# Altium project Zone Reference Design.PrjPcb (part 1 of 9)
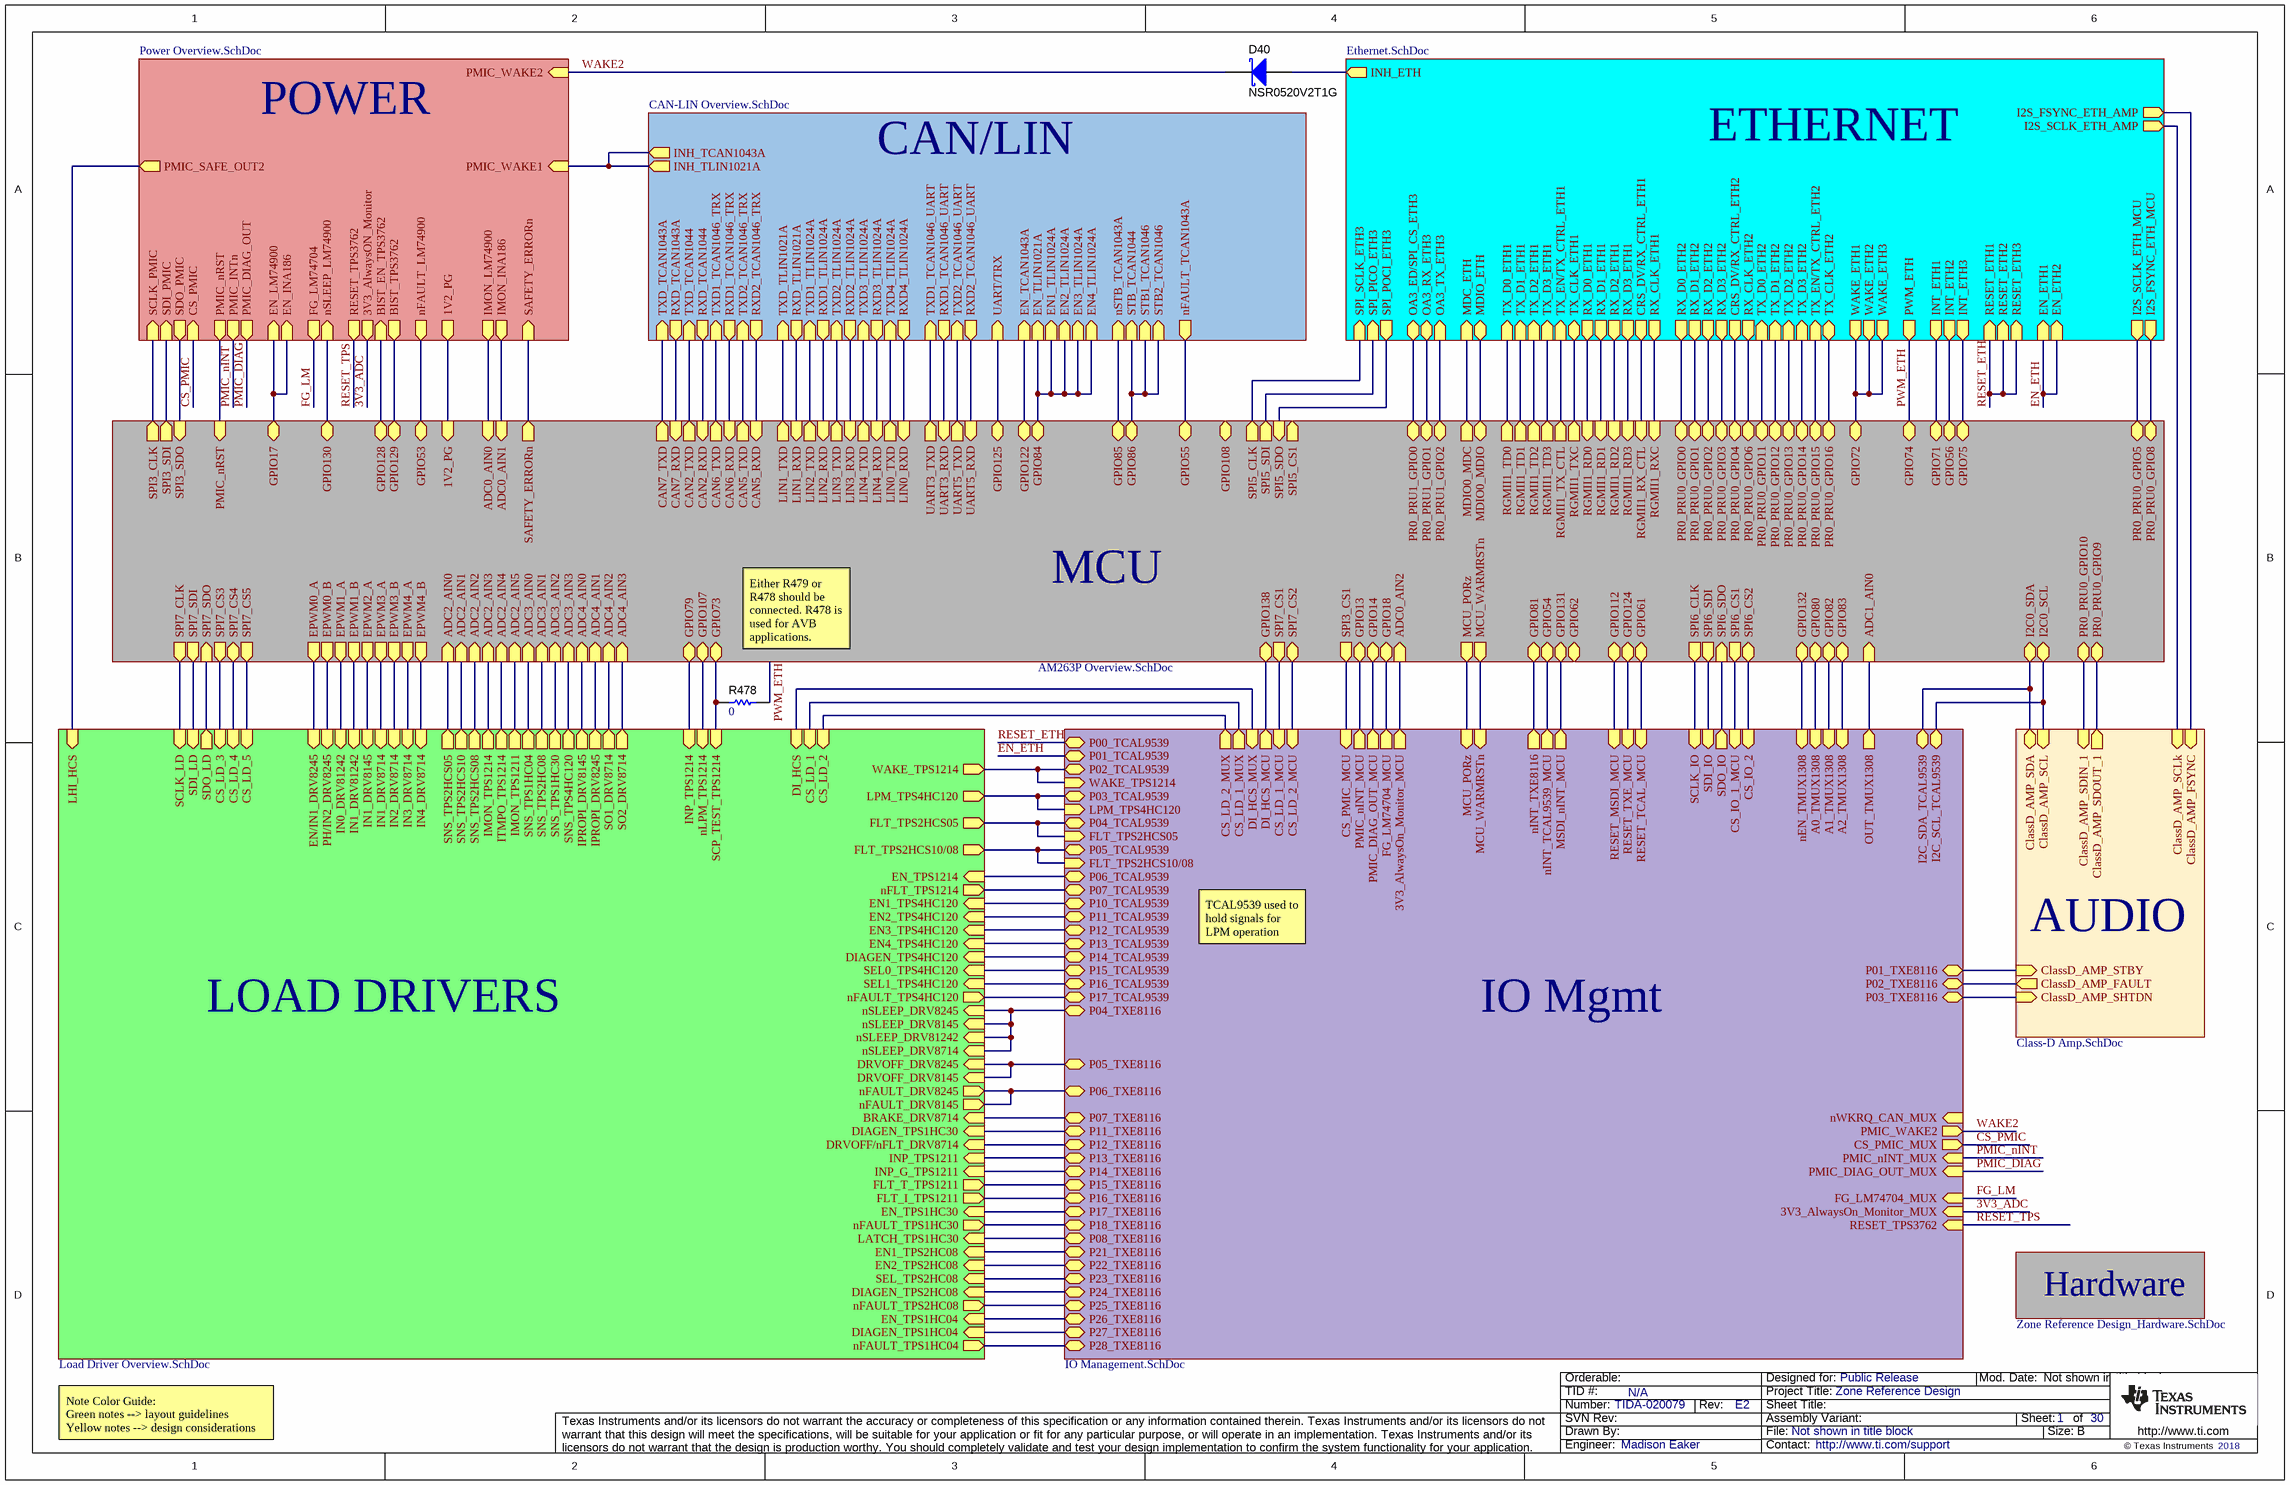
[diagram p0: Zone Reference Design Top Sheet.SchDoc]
CopyrightYear: 2018; PCB_Layout: Krypton Solutions; PCB_Rev: E2; PRJ_Customer: Public Release; PRJ_Engineer: Madison Eaker; PRJ_Number: TIDA-020079; PRJ_Title: Zone Reference Design; SCH_Rev: E2; TechSupport: http://www.ti.com/support; TID: N/A
30 sheets, 1132 parts. Net scope: hierarchical (ports join the sheet entries above them; power ports are global).
Board file: Zone Reference Design.PcbDoc
Sheets:
  Zone Reference Design Top Sheet.SchDoc
    POWER = Power Overview.SchDoc
      Power ORing = Input Supply.SchDoc
      PMIC = PMIC.SchDoc
      Extra Power = BUCKs and LDO.SchDoc
    LOAD DRIVERS = Load Driver Overview.SchDoc
      Standard HSS = High Side Switches.SchDoc
      Half Bridge Gate Driver = DRV8714S-Q1.SchDoc
      H-Bridge, Half Bridge, HS/LS = DRV8x45S-Q1 and DRV81242-Q1.SchDoc
      Standard HSSC = TPS1211-Q1.SchDoc
      Smart Fuse HSS = Smart Fuse HSS.SchDoc
      Smart Fuse HSSC = TPS1214-Q1.SchDoc
    CAN/LIN = CAN-LIN Overview.SchDoc
      TLIN1021A and TLIN1024A = LIN.SchDoc
      TCAN1043A and TCAN1044V = CAN1.SchDoc
      TCAN1046AV = CAN2.SchDoc
    IO Mgmt = IO Management.SchDoc
      MUXes and TPLD = MUXes and TPLD.SchDoc
      MSDI = TIC12400-Q1.SchDoc
      IO Expanders = IO Expanders.SchDoc
    MCU = AM263P Overview.SchDoc
      RESET CIRCUIT = AM263P Reset Circuit.SchDoc
      AM263Px Power Caps = AM263P Power Caps.SchDoc
      Temp Sensor/EEPROM = AM263P Temp and EEPROM.SchDoc
      OSPI Bootmode = AM263P OSPI Bootmode.SchDoc
      ADC = AM263P ADC.SchDoc
      AM263Px IO = AM263P PRU_EPWM.SchDoc
    ETHERNET = Ethernet.SchDoc
    AUDIO = Class-D Amp.SchDoc
    Hardware = Zone Reference Design_Hardware.SchDoc

## Sheet Zone Reference Design Top Sheet.SchDoc
size 431 x 279 mm; Date: Not shown in title block; ApprovedBy: Not shown in title block; CheckedBy: Not shown in title block; Author: Not shown in title block; CompanyName: Not shown in title block; Engineer: Not shown in title block; Organization: Not shown in title block; Address1: Not shown in title block; Address2: Not shown in title block; Address3: Not shown in title block; Address4: Not shown in title block; DocumentNumber: 1; Revision: Use project parameter SCH_Rev; SheetNumber: 1; SheetTotal: 30; PageSetup: Record=PageOptions¦CenterHorizontal=True¦CenterVertical=True¦PrintScale=1.00¦XCorrection=1.00¦YCorrection=1.00¦PrintKind=0¦BorderSize=5000000¦LeftOffset=0¦BottomOffset=0¦Orientation=2¦PaperLength=1000¦PaperWidth=1000¦Scale=100¦PaperSource=15¦PrintQuality=600¦MediaType=1¦DitherType=10¦PaperKind=Letter¦PrintScaleMode=1

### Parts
D40  NSR0520V2T1G  [SOD-523]
R478  ValueDisplayed: 0  [0603]  (hidden comment: RC0603JR-070RL)

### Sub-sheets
AUDIO = Class-D Amp.SchDoc: ClassD_AMP_SHTDN (in), ClassD_AMP_SDA (bidir), ClassD_AMP_SCL (in), ClassD_AMP_STBY (in), ClassD_AMP_FAULT (out), ClassD_AMP_SCLk (in), ClassD_AMP_FSYNC (in), ClassD_AMP_SDIN_1 (in), ClassD_AMP_SDOUT_1 (out)
CAN/LIN = CAN-LIN Overview.SchDoc: TXD_TCAN1043A (in), RXD_TCAN1043A (out), TXD_TCAN1044 (in), RXD_TCAN1044 (out), EN_TCAN1043A (in), nSTB_TCAN1043A (in), STB_TCAN1044 (in), STB1_TCAN1046 (in), STB2_TCAN1046 (in), UART/TRX (in), TXD1_TCAN1046_UART (in), RXD1_TCAN1046_UART (out), TXD1_TCAN1046_TRX (in), RXD1_TCAN1046_TRX (out), TXD2_TCAN1046_UART (in), RXD2_TCAN1046_UART (out), TXD2_TCAN1046_TRX (in), RXD2_TCAN1046_TRX (out), TXD_TLIN1021A (in), RXD_TLIN1021A (out), TXD1_TLIN1024A (in), RXD1_TLIN1024A (out), TXD2_TLIN1024A (in), RXD2_TLIN1024A (out), TXD3_TLIN1024A (in), RXD3_TLIN1024A (out), TXD4_TLIN1024A (in), RXD4_TLIN1024A (out), EN_TLIN1021A (in), EN1_TLIN1024A (in), EN2_TLIN1024A (in), EN3_TLIN1024A (in), EN4_TLIN1024A (in), INH_TCAN1043A (out), nFAULT_TCAN1043A (out), INH_TLIN1021A (out)
ETHERNET = Ethernet.SchDoc: RX_D3_ETH1 (out), RX_D2_ETH1 (out), RX_D1_ETH1 (out), RX_D0_ETH1 (out), RX_CLK_ETH1 (out), CRS_DV/RX_CTRL_ETH1 (out), TX_CLK_ETH1 (bidir), TX_EN/TX_CTRL_ETH1 (in), TX_D3_ETH1 (in), TX_D2_ETH1 (in), TX_D1_ETH1 (in), TX_D0_ETH1 (in), INT_ETH1 (out), WAKE_ETH1 (out), PWM_ETH (out), RESET_ETH1 (in), EN_ETH1 (in), MDIO_ETH (bidir), MDC_ETH (in), INH_ETH (out), RX_D3_ETH2 (out), RX_D2_ETH2 (out), RX_D1_ETH2 (out), RX_D0_ETH2 (out), RX_CLK_ETH2 (out), CRS_DV/RX_CTRL_ETH2 (out), TX_CLK_ETH2 (bidir), TX_EN/TX_CTRL_ETH2 (in), TX_D3_ETH2 (in), TX_D2_ETH2 (in), TX_D1_ETH2 (in), TX_D0_ETH2 (in), SPI_SCLK_ETH3 (in), SPI_PICO_ETH3 (in), SPI_POCI_ETH3 (out), OA3_TX_ETH3 (in), OA3_RX_ETH3 (bidir), INT_ETH3 (out), RESET_ETH3 (in), WAKE_ETH3 (out), INT_ETH2 (out), WAKE_ETH2 (out), RESET_ETH2 (in), EN_ETH2 (in), OA3_ED/SPI_CS_ETH3 (bidir), I2S_FSYNC_ETH_AMP (out), I2S_FSYNC_ETH_MCU (out), I2S_SCLK_ETH_AMP (out), I2S_SCLK_ETH_MCU (out)
Hardware = Zone Reference Design_Hardware.SchDoc: no entries
IO Mgmt = IO Management.SchDoc: SCLK_IO (in), SDI_IO (in), SDO_IO (out), nEN_TMUX1308 (in), A0_TMUX1308 (in), A1_TMUX1308 (in), A2_TMUX1308 (in), OUT_TMUX1308 (out), MSDI_nINT_MCU (out), I2C_SCL_TCAL9539 (bidir), I2C_SDA_TCAL9539 (bidir), PMIC_WAKE2 (out), nINT_TXE8116 (out), CS_IO_2 (in), P01_TXE8116 (bidir), P02_TXE8116 (bidir), P03_TXE8116 (bidir), P04_TXE8116 (bidir), P05_TXE8116 (bidir), P06_TXE8116 (bidir), P07_TXE8116 (bidir), P11_TXE8116 (bidir), P12_TXE8116 (bidir), P13_TXE8116 (bidir), P14_TXE8116 (bidir), P15_TXE8116 (bidir), P16_TXE8116 (bidir), P17_TXE8116 (bidir), P08_TXE8116 (bidir), P18_TXE8116 (bidir), P10_TCAL9539 (bidir), P11_TCAL9539 (bidir), P12_TCAL9539 (bidir), P13_TCAL9539 (bidir), P14_TCAL9539 (bidir), P15_TCAL9539 (bidir), P16_TCAL9539 (bidir), P17_TCAL9539 (bidir), P00_TCAL9539 (bidir), P01_TCAL9539 (bidir), P02_TCAL9539 (bidir), P03_TCAL9539 (bidir), P04_TCAL9539 (bidir), P05_TCAL9539 (bidir), P06_TCAL9539 (bidir), P07_TCAL9539 (bidir), P21_TXE8116 (bidir), P22_TXE8116 (bidir), P23_TXE8116 (bidir), P24_TXE8116 (bidir), P25_TXE8116 (bidir), P26_TXE8116 (bidir), P27_TXE8116 (bidir), P28_TXE8116 (bidir), nINT_TCAL9539_MCU (out), MCU_PORz (in), MCU_WARMRSTn (in), RESET_TCAL_MCU (in), RESET_TXE_MCU (in), DI_HCS_MUX (in), DI_HCS_MCU (out), CS_LD_1_MUX (out), CS_LD_2_MUX (out), CS_PMIC_MUX (out), PMIC_DIAG_OUT_MUX (in), FG_LM74704_MUX (in), 3V3_AlwaysOn_Monitor_MUX (in), LPM_TPS4HC120 (in), WAKE_TPS1214 (in), FLT_TPS2HCS05 (in), RESET_TPS3762 (in), CS_LD_1_MCU (in), CS_LD_2_MCU (in), CS_IO_1_MCU (in), CS_PMIC_MCU (in), PMIC_nINT_MUX (in), PMIC_DIAG_OUT_MCU (out), FG_LM74704_MCU (out), 3V3_AlwaysOn_Monitor_MCU (out), PMIC_nINT_MCU (out), RESET_MSDI_MCU (in), FLT_TPS2HCS10/08  (in), nWKRQ_CAN_MUX (in)
LOAD DRIVERS = Load Driver Overview.SchDoc: SNS_TPS2HCS05 (out), SNS_TPS2HCS10 (out), SNS_TPS2HCS08 (out), IMON_TPS1214 (out), ITMPO_TPS1214 (out), WAKE_TPS1214 (out), FLT_TPS2HCS05 (out), FLT_TPS2HCS10/08 (out), SDO_LD (out), IMON_TPS1211 (out), FLT_T_TPS1211 (out), FLT_I_TPS1211 (out), SNS_TPS4HC120 (out), SNS_TPS1HC30 (out), SNS_TPS2HC08 (out), SNS_TPS1HC04 (out), LPM_TPS4HC120 (out), nFAULT_TPS2HC08 (out), nFAULT_TPS1HC04 (out), SCLK_LD (in), SDI_LD (in), CS_LD_1 (in), CS_LD_2 (in), nLPM_TPS1214 (in), LHI_HCS (in), DI_HCS (in), nFAULT_DRV8245 (out), nFAULT_DRV8145 (out), IPROPI_DRV8145 (out), IPROPI_DRV8245 (out), CS_LD_3 (in), CS_LD_4 (in), EN/IN1_DRV8245 (in), PH/IN2_DRV8245 (in), IN1_DRV8145 (in), IN0_DRV81242 (in), IN1_DRV81242 (in), CS_LD_5 (in), IN1_DRV8714 (in), IN2_DRV8714 (in), IN3_DRV8714 (in), IN4_DRV8714 (in), DRVOFF/nFLT_DRV8714 (in), EN1_TPS4HC120 (in), EN2_TPS4HC120 (in), EN3_TPS4HC120 (in), EN4_TPS4HC120 (in), SEL1_TPS4HC120 (in), SEL0_TPS4HC120 (in), SO1_DRV8714 (out), SO2_DRV8714 (out), nFLT_TPS1214 (out), EN_TPS1HC30 (in), LATCH_TPS1HC30 (in), EN1_TPS2HC08 (in), EN2_TPS2HC08 (in), SEL_TPS2HC08 (in), DIAGEN_TPS2HC08 (in), EN_TPS1HC04 (in), DIAGEN_TPS1HC04 (in), DIAGEN_TPS4HC120 (in), DIAGEN_TPS1HC30 (in), BRAKE_DRV8714 (in), nFAULT_TPS1HC30 (out), nFAULT_TPS4HC120 (out), EN_TPS1214 (in), INP_TPS1214 (in), SCP_TEST_TPS1214 (in), INP_TPS1211 (in), INP_G_TPS1211 (in), nSLEEP_DRV8245 (in), nSLEEP_DRV8145 (in), nSLEEP_DRV81242 (in), DRVOFF_DRV8245 (in), DRVOFF_DRV8145 (in), nSLEEP_DRV8714 (in)
MCU = AM263P Overview.SchDoc: LIN1_RXD (in), LIN1_TXD (out), LIN2_RXD (in), LIN2_TXD (out), LIN3_RXD (in), LIN3_TXD (out), LIN4_RXD (in), LIN4_TXD (out), LIN0_RXD (in), LIN0_TXD (out), CAN7_RXD (in), CAN7_TXD (out), CAN2_RXD (in), CAN2_TXD (out), CAN6_RXD (in), CAN6_TXD (out), CAN5_RXD (in), CAN5_TXD (out), UART3_RXD (in), UART3_TXD (out), UART5_RXD (in), UART5_TXD (out), I2C0_SCL (bidir), I2C0_SDA (bidir), SPI5_CLK (out), SPI5_CS1 (out), SPI5_SDI (out), SPI5_SDO (in), SPI7_CLK (out), SPI7_CS1 (out), SPI7_SDI (out), SPI7_SDO (in), SPI3_CLK (out), SPI3_CS1 (out), SPI3_SDI (out), SPI3_SDO (in), SPI6_CLK (out), SPI6_CS1 (out), SPI6_SDI (out), SPI6_SDO (in), EPWM0_A (out), EPWM0_B (out), EPWM1_A (out), EPWM1_B (out), EPWM2_A (out), EPWM3_A (out), EPWM3_B (out), EPWM4_A (out), EPWM4_B (out), GPIO53 (bidir), GPIO54 (bidir), GPIO55 (bidir), GPIO56 (bidir), ADC0_AIN0 (in), ADC0_AIN1 (in), ADC1_AIN0 (in), ADC2_AIN0 (in), ADC2_AIN1 (in), ADC2_AIN2 (in), ADC2_AIN3 (in), ADC2_AIN4 (in), ADC2_AIN5 (in), ADC4_AIN0 (in), ADC4_AIN1 (in), ADC4_AIN2 (in), ADC4_AIN3 (in), ADC3_AIN0 (in), ADC3_AIN1 (in), ADC3_AIN2 (in), ADC3_AIN3 (in), SPI7_CS2 (bidir), GPIO17 (bidir), GPIO18 (bidir), GPIO79 (bidir), SPI6_CS2 (bidir), GPIO61 (bidir), GPIO62 (bidir), SPI7_CS3 (out), SPI7_CS4 (bidir), GPIO71 (bidir), GPIO72 (bidir), GPIO73 (bidir), GPIO74 (bidir), GPIO80 (bidir), GPIO82 (bidir), GPIO83 (bidir), GPIO84 (bidir), GPIO107 (bidir), GPIO108 (bidir), GPIO112 (bidir), GPIO122 (bidir), GPIO124 (bidir), GPIO125 (bidir), GPIO129 (bidir), GPIO130 (bidir), GPIO131 (bidir), GPIO132 (bidir), GPIO138 (bidir), GPIO81 (bidir), SAFETY_ERRORn (out), MDIO0_MDC (out), MDIO0_MDIO (bidir), RGMII1_RD0 (in), RGMII1_RD2 (in), RGMII1_RD1 (in), RGMII1_RD3 (in), RGMII1_RX_CTL (in), RGMII1_RXC (in), RGMII1_TD0 (out), RGMII1_TD1 (out), RGMII1_TD2 (out), RGMII1_TD3 (out), RGMII1_TX_CTL (out), RGMII1_TXC (out), GPIO86 (bidir), GPIO85 (bidir), PR0_PRU0_GPIO0 (bidir), PR0_PRU0_GPIO1 (bidir), PR0_PRU0_GPIO2 (bidir), PR0_PRU0_GPIO3 (bidir), PR0_PRU0_GPIO4 (bidir), PR0_PRU0_GPIO5 (bidir), PR0_PRU0_GPIO6 (bidir), PR0_PRU0_GPIO8 (bidir), PR0_PRU0_GPIO9 (bidir), PR0_PRU0_GPIO10 (bidir), PR0_PRU0_GPIO11 (bidir), PR0_PRU0_GPIO12 (bidir), PR0_PRU0_GPIO13 (bidir), PR0_PRU0_GPIO14 (bidir), PR0_PRU0_GPIO15 (bidir), PR0_PRU0_GPIO16 (bidir), PR0_PRU1_GPIO0 (bidir), PR0_PRU1_GPIO1 (bidir), PR0_PRU1_GPIO2 (bidir), PMIC_nRST (in), 1V2_PG (in), GPIO13 (bidir), GPIO14 (bidir), SPI7_CS5 (out), GPIO128 (bidir), GPIO75 (bidir), MCU_PORz (out), MCU_WARMRSTn (out), ADC0_AIN2 (in)
POWER = Power Overview.SchDoc: EN_LM74900 (in), EN_INA186 (in), nSLEEP_LM74900 (in), IMON_INA186 (out), IMON_LM74900 (out), FG_LM74704 (out), nFAULT_LM74900 (out), SCLK_PMIC (in), SDI_PMIC (in), CS_PMIC (in), PMIC_WAKE2 (in), PMIC_WAKE1 (in), SAFETY_ERRORn (in), BIST_EN_TPS3762 (in), RESET_TPS3762 (out), BIST_TPS3762 (out), 1V2_PG (out), PMIC_SAFE_OUT2 (out), PMIC_nRST (out), PMIC_INTn (out), PMIC_DIAG_OUT (out), SDO_PMIC (out), 3V3_AlwaysON_Monitor (out)

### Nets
1V2_PG: sheet POWER/1V2_PG, sheet MCU/1V2_PG
3V3_ADC: sheet POWER/3V3_AlwaysON_Monitor, sheet IO Mgmt/3V3_AlwaysOn_Monitor_MUX
3V3_AlwaysOn_Monitor_MCU: sheet IO Mgmt/3V3_AlwaysOn_Monitor_MCU, sheet MCU/ADC0_AIN2
A0_TMUX1308: sheet IO Mgmt/A0_TMUX1308, sheet MCU/GPIO80
A1_TMUX1308: sheet IO Mgmt/A1_TMUX1308, sheet MCU/GPIO82
A2_TMUX1308: sheet IO Mgmt/A2_TMUX1308, sheet MCU/GPIO83
ADC0_AIN0: sheet POWER/IMON_LM74900, sheet MCU/ADC0_AIN0
ADC0_AIN1: sheet POWER/IMON_INA186, sheet MCU/ADC0_AIN1
ADC1_AIN0: sheet IO Mgmt/OUT_TMUX1308, sheet MCU/ADC1_AIN0
ADC2_AIN0: sheet LOAD DRIVERS/SNS_TPS2HCS05, sheet MCU/ADC2_AIN0
ADC2_AIN1: sheet LOAD DRIVERS/SNS_TPS2HCS10, sheet MCU/ADC2_AIN1
ADC2_AIN2: sheet LOAD DRIVERS/SNS_TPS2HCS08, sheet MCU/ADC2_AIN2
ADC2_AIN5: sheet LOAD DRIVERS/IMON_TPS1211, sheet MCU/ADC2_AIN5
ADC3_AIN0: sheet LOAD DRIVERS/SNS_TPS1HC04, sheet MCU/ADC3_AIN0
ADC3_AIN1: sheet LOAD DRIVERS/SNS_TPS2HC08, sheet MCU/ADC3_AIN1
ADC3_AIN2: sheet LOAD DRIVERS/SNS_TPS1HC30, sheet MCU/ADC3_AIN2
ADC3_AIN3: sheet LOAD DRIVERS/SNS_TPS4HC120, sheet MCU/ADC3_AIN3
ADC4_AIN0: sheet LOAD DRIVERS/IPROPI_DRV8145, sheet MCU/ADC4_AIN0
ADC4_AIN1: sheet LOAD DRIVERS/IPROPI_DRV8245, sheet MCU/ADC4_AIN1
ADC4_AIN2: sheet LOAD DRIVERS/SO1_DRV8714, sheet MCU/ADC4_AIN2
ADC4_AIN3: sheet LOAD DRIVERS/SO2_DRV8714, sheet MCU/ADC4_AIN3
BIST_EN_TPS3762: sheet POWER/BIST_EN_TPS3762, sheet MCU/GPIO128
BIST_TPS3762: sheet POWER/BIST_TPS3762, sheet MCU/GPIO129
BRAKE_DRV8714: sheet LOAD DRIVERS/BRAKE_DRV8714, sheet IO Mgmt/P07_TXE8116
CAN2_RXD: sheet CAN/LIN/RXD_TCAN1044, sheet MCU/CAN2_RXD
CAN2_TXD: sheet CAN/LIN/TXD_TCAN1044, sheet MCU/CAN2_TXD
CAN5_RXD: sheet CAN/LIN/RXD2_TCAN1046_TRX, sheet MCU/CAN5_RXD
CAN5_TXD: sheet CAN/LIN/TXD2_TCAN1046_TRX, sheet MCU/CAN5_TXD
CAN6_RXD: sheet CAN/LIN/RXD1_TCAN1046_TRX, sheet MCU/CAN6_RXD
CAN6_TXD: sheet CAN/LIN/TXD1_TCAN1046_TRX, sheet MCU/CAN6_TXD
CAN7_RXD: sheet CAN/LIN/RXD_TCAN1043A, sheet MCU/CAN7_RXD
CAN7_TXD: sheet CAN/LIN/TXD_TCAN1043A, sheet MCU/CAN7_TXD
ClassD_AMP_FAULT: sheet IO Mgmt/P02_TXE8116, sheet AUDIO/ClassD_AMP_FAULT
ClassD_AMP_FSYNC: sheet ETHERNET/I2S_FSYNC_ETH_AMP, sheet AUDIO/ClassD_AMP_FSYNC
ClassD_AMP_SCLk: sheet ETHERNET/I2S_SCLK_ETH_AMP, sheet AUDIO/ClassD_AMP_SCLk
ClassD_AMP_SDIN_1: sheet MCU/PR0_PRU0_GPIO10, sheet AUDIO/ClassD_AMP_SDIN_1
ClassD_AMP_SDOUT_1: sheet MCU/PR0_PRU0_GPIO9, sheet AUDIO/ClassD_AMP_SDOUT_1
ClassD_AMP_SHTDN: sheet IO Mgmt/P03_TXE8116, sheet AUDIO/ClassD_AMP_SHTDN
ClassD_AMP_STBY: sheet IO Mgmt/P01_TXE8116, sheet AUDIO/ClassD_AMP_STBY
CRS_DV/RX_CTRL_ETH1: sheet MCU/RGMII1_RX_CTL, sheet ETHERNET/CRS_DV/RX_CTRL_ETH1
CRS_DV/RX_CTRL_ETH2: sheet MCU/PR0_PRU0_GPIO4, sheet ETHERNET/CRS_DV/RX_CTRL_ETH2
CS_IO: sheet IO Mgmt/CS_IO_2, sheet MCU/SPI6_CS2
CS_IO_1_MCU: sheet IO Mgmt/CS_IO_1_MCU, sheet MCU/SPI6_CS1
CS_LD_1: sheet LOAD DRIVERS/CS_LD_1, sheet IO Mgmt/CS_LD_1_MUX
CS_LD_1_MCU: sheet IO Mgmt/CS_LD_1_MCU, sheet MCU/SPI7_CS1
CS_LD_2: sheet LOAD DRIVERS/CS_LD_2, sheet IO Mgmt/CS_LD_2_MUX
CS_LD_4: sheet LOAD DRIVERS/CS_LD_4, sheet MCU/SPI7_CS4
CS_PMIC: sheet POWER/CS_PMIC, sheet IO Mgmt/CS_PMIC_MUX
CS_PMIC_MCU: sheet IO Mgmt/CS_PMIC_MCU, sheet MCU/SPI3_CS1
DI_HCS: sheet LOAD DRIVERS/DI_HCS, sheet IO Mgmt/DI_HCS_MUX
DI_HCS_MCU: sheet IO Mgmt/DI_HCS_MCU, sheet MCU/GPIO138
DIAGEN_TPS1HC04: sheet LOAD DRIVERS/DIAGEN_TPS1HC04, sheet IO Mgmt/P27_TXE8116
DIAGEN_TPS1HC30: sheet LOAD DRIVERS/DIAGEN_TPS1HC30, sheet IO Mgmt/P11_TXE8116
DIAGEN_TPS2HC08: sheet LOAD DRIVERS/DIAGEN_TPS2HC08, sheet IO Mgmt/P24_TXE8116
DIAGEN_TPS4HC120: sheet LOAD DRIVERS/DIAGEN_TPS4HC120, sheet IO Mgmt/P14_TCAL9539
DRVOFF_DRV8145: sheet LOAD DRIVERS/DRVOFF_DRV8245, sheet LOAD DRIVERS/DRVOFF_DRV8145, sheet IO Mgmt/P05_TXE8116
EN1_TLIN1024A: sheet CAN/LIN/EN_TLIN1021A, sheet CAN/LIN/EN1_TLIN1024A, sheet CAN/LIN/EN2_TLIN1024A, sheet CAN/LIN/EN3_TLIN1024A, sheet CAN/LIN/EN4_TLIN1024A, sheet MCU/GPIO84
EN1_TPS2HC08: sheet LOAD DRIVERS/EN1_TPS2HC08, sheet IO Mgmt/P21_TXE8116
EN1_TPS4HC120: sheet LOAD DRIVERS/EN1_TPS4HC120, sheet IO Mgmt/P10_TCAL9539
EN2_TPS2HC08: sheet LOAD DRIVERS/EN2_TPS2HC08, sheet IO Mgmt/P22_TXE8116
EN2_TPS4HC120: sheet LOAD DRIVERS/EN2_TPS4HC120, sheet IO Mgmt/P11_TCAL9539
EN3_TPS4HC120: sheet LOAD DRIVERS/EN3_TPS4HC120, sheet IO Mgmt/P12_TCAL9539
EN4_TPS4HC120: sheet LOAD DRIVERS/EN4_TPS4HC120, sheet IO Mgmt/P13_TCAL9539
EN/IN1_DRV8245: sheet LOAD DRIVERS/EN/IN1_DRV8245, sheet MCU/EPWM0_A
EN_ETH: sheet IO Mgmt/P01_TCAL9539, sheet ETHERNET/EN_ETH1, sheet ETHERNET/EN_ETH2
EN_INA186: sheet POWER/EN_LM74900, sheet POWER/EN_INA186, sheet MCU/GPIO17
EN_TCAN1043A: sheet CAN/LIN/EN_TCAN1043A, sheet MCU/GPIO122
EN_TPS1HC04: sheet LOAD DRIVERS/EN_TPS1HC04, sheet IO Mgmt/P26_TXE8116
EN_TPS1HC30: sheet LOAD DRIVERS/EN_TPS1HC30, sheet IO Mgmt/P17_TXE8116
EN_TPS1214: sheet LOAD DRIVERS/EN_TPS1214, sheet IO Mgmt/P06_TCAL9539
EPWM0_B: sheet LOAD DRIVERS/PH/IN2_DRV8245, sheet MCU/EPWM0_B
EPWM1_A: sheet LOAD DRIVERS/IN0_DRV81242, sheet MCU/EPWM1_A
EPWM1_B: sheet LOAD DRIVERS/IN1_DRV81242, sheet MCU/EPWM1_B
EPWM2_A: sheet LOAD DRIVERS/IN1_DRV8145, sheet MCU/EPWM2_A
EPWM3_A: sheet LOAD DRIVERS/IN1_DRV8714, sheet MCU/EPWM3_A
EPWM3_B: sheet LOAD DRIVERS/IN2_DRV8714, sheet MCU/EPWM3_B
EPWM4_A: sheet LOAD DRIVERS/IN3_DRV8714, sheet MCU/EPWM4_A
EPWM4_B: sheet LOAD DRIVERS/IN4_DRV8714, sheet MCU/EPWM4_B
EPWM5_A: sheet POWER/nFAULT_LM74900, sheet MCU/GPIO53
EPWM5_B: sheet IO Mgmt/nINT_TCAL9539_MCU, sheet MCU/GPIO54
EPWM6_A: sheet CAN/LIN/nFAULT_TCAN1043A, sheet MCU/GPIO55
EPWM6_B: sheet MCU/GPIO56, sheet ETHERNET/INT_ETH2
EPWM9_A: sheet IO Mgmt/RESET_TCAL_MCU, sheet MCU/GPIO61
EPWM_14A: sheet MCU/GPIO71, sheet ETHERNET/INT_ETH1
EPWM_14B: sheet MCU/GPIO72, sheet ETHERNET/WAKE_ETH1, sheet ETHERNET/WAKE_ETH3, sheet ETHERNET/WAKE_ETH2
EPWM_15A: R478.1 ; sheet LOAD DRIVERS/SCP_TEST_TPS1214, sheet MCU/GPIO73
EQEP0_A: sheet POWER/nSLEEP_LM74900, sheet MCU/GPIO130
EQEP0_B: sheet IO Mgmt/MSDI_nINT_MCU, sheet MCU/GPIO131
EQEP0_STROBE: sheet IO Mgmt/nEN_TMUX1308, sheet MCU/GPIO132
FG_LM: sheet POWER/FG_LM74704, sheet IO Mgmt/FG_LM74704_MUX  [project net FETGOOD]
FG_LM74704_MCU: sheet IO Mgmt/FG_LM74704_MCU, sheet MCU/GPIO18
FLT/: sheet LOAD DRIVERS/nFLT_TPS1214, sheet IO Mgmt/P07_TCAL9539
FLT_I_TPS1211: sheet LOAD DRIVERS/FLT_I_TPS1211, sheet IO Mgmt/P16_TXE8116
FLT_T_TPS1211: sheet LOAD DRIVERS/FLT_T_TPS1211, sheet IO Mgmt/P15_TXE8116
FLT_TPS2HCS05: sheet LOAD DRIVERS/FLT_TPS2HCS05, sheet IO Mgmt/P04_TCAL9539, sheet IO Mgmt/FLT_TPS2HCS05
FLT_TPS2HCS10/08: sheet LOAD DRIVERS/FLT_TPS2HCS10/08, sheet IO Mgmt/P05_TCAL9539, sheet IO Mgmt/FLT_TPS2HCS10/08 
GPIO14: sheet IO Mgmt/PMIC_DIAG_OUT_MCU, sheet MCU/GPIO14
GPIO75: sheet MCU/GPIO75, sheet ETHERNET/INT_ETH3
GPIO79: sheet LOAD DRIVERS/INP_TPS1214, sheet MCU/GPIO79
GPIO81: sheet IO Mgmt/nINT_TXE8116, sheet MCU/GPIO81
GPIO85: sheet CAN/LIN/nSTB_TCAN1043A, sheet MCU/GPIO85
GPIO86: sheet CAN/LIN/STB_TCAN1044, sheet CAN/LIN/STB1_TCAN1046, sheet CAN/LIN/STB2_TCAN1046, sheet MCU/GPIO86
GPIO107: sheet LOAD DRIVERS/nLPM_TPS1214, sheet MCU/GPIO107
GPIO112: sheet IO Mgmt/RESET_MSDI_MCU, sheet MCU/GPIO112
GPIO124: sheet IO Mgmt/RESET_TXE_MCU, sheet MCU/GPIO124
GPIO125: sheet CAN/LIN/UART/TRX, sheet MCU/GPIO125
I2C0_SCL: sheet IO Mgmt/I2C_SCL_TCAL9539, sheet MCU/I2C0_SCL, sheet AUDIO/ClassD_AMP_SCL
I2C0_SDA: sheet IO Mgmt/I2C_SDA_TCAL9539, sheet MCU/I2C0_SDA, sheet AUDIO/ClassD_AMP_SDA
I2S_FSYNC_ETH_MCU: sheet MCU/PR0_PRU0_GPIO8, sheet ETHERNET/I2S_FSYNC_ETH_MCU
I2S_SCLK_ETH_MCU: sheet MCU/PR0_PRU0_GPIO5, sheet ETHERNET/I2S_SCLK_ETH_MCU
IMON: sheet LOAD DRIVERS/IMON_TPS1214, sheet MCU/ADC2_AIN3
INH_ETH: D40.2(A) ; sheet ETHERNET/INH_ETH
INH_TCAN1043A: sheet POWER/PMIC_WAKE1, sheet CAN/LIN/INH_TCAN1043A, sheet CAN/LIN/INH_TLIN1021A
INP_G_TPS1211: sheet LOAD DRIVERS/INP_G_TPS1211, sheet IO Mgmt/P14_TXE8116
INP_TPS1211: sheet LOAD DRIVERS/INP_TPS1211, sheet IO Mgmt/P13_TXE8116
ITMPO: sheet LOAD DRIVERS/ITMPO_TPS1214, sheet MCU/ADC2_AIN4
LATCH_TPS1HC30: sheet LOAD DRIVERS/LATCH_TPS1HC30, sheet IO Mgmt/P08_TXE8116
LHI_HCS: sheet POWER/PMIC_SAFE_OUT2, sheet LOAD DRIVERS/LHI_HCS
LIN0_RXD: sheet CAN/LIN/RXD4_TLIN1024A, sheet MCU/LIN0_RXD
LIN0_TXD: sheet CAN/LIN/TXD4_TLIN1024A, sheet MCU/LIN0_TXD
LIN1_RXD: sheet CAN/LIN/RXD_TLIN1021A, sheet MCU/LIN1_RXD
LIN1_TXD: sheet CAN/LIN/TXD_TLIN1021A, sheet MCU/LIN1_TXD
LIN2_RXD: sheet CAN/LIN/RXD1_TLIN1024A, sheet MCU/LIN2_RXD
LIN2_TXD: sheet CAN/LIN/TXD1_TLIN1024A, sheet MCU/LIN2_TXD
LIN3_RXD: sheet CAN/LIN/RXD2_TLIN1024A, sheet MCU/LIN3_RXD
LIN4_RXD: sheet CAN/LIN/RXD3_TLIN1024A, sheet MCU/LIN4_RXD
LIN4_TXD: sheet CAN/LIN/TXD3_TLIN1024A, sheet MCU/LIN4_TXD
LPM_TPS4HC120: sheet LOAD DRIVERS/LPM_TPS4HC120, sheet IO Mgmt/P03_TCAL9539, sheet IO Mgmt/LPM_TPS4HC120
MCU_PORz: sheet IO Mgmt/MCU_PORz, sheet MCU/MCU_PORz
MCU_WARMRSTn: sheet IO Mgmt/MCU_WARMRSTn, sheet MCU/MCU_WARMRSTn
MDC_ETH: sheet MCU/MDIO0_MDC, sheet ETHERNET/MDC_ETH
MDIO_ETH: sheet MCU/MDIO0_MDIO, sheet ETHERNET/MDIO_ETH
nCS: sheet LOAD DRIVERS/CS_LD_3, sheet MCU/SPI7_CS3
nFAULT_DRV8145: sheet LOAD DRIVERS/nFAULT_DRV8245, sheet LOAD DRIVERS/nFAULT_DRV8145, sheet IO Mgmt/P06_TXE8116
nFAULT_TPS1HC04: sheet LOAD DRIVERS/nFAULT_TPS1HC04, sheet IO Mgmt/P28_TXE8116
nFAULT_TPS1HC30: sheet LOAD DRIVERS/nFAULT_TPS1HC30, sheet IO Mgmt/P18_TXE8116
nFAULT_TPS2HC08: sheet LOAD DRIVERS/nFAULT_TPS2HC08, sheet IO Mgmt/P25_TXE8116
nFAULT_TPS4HC120: sheet LOAD DRIVERS/nFAULT_TPS4HC120, sheet IO Mgmt/P17_TCAL9539
nFLT_DRV8714: sheet LOAD DRIVERS/DRVOFF/nFLT_DRV8714, sheet IO Mgmt/P12_TXE8116
nSLEEP_DRV81242: sheet LOAD DRIVERS/nSLEEP_DRV8245, sheet LOAD DRIVERS/nSLEEP_DRV8145, sheet LOAD DRIVERS/nSLEEP_DRV81242, sheet LOAD DRIVERS/nSLEEP_DRV8714, sheet IO Mgmt/P04_TXE8116
OA3_ED/SPI_CS_ETH3: sheet MCU/PR0_PRU1_GPIO0, sheet ETHERNET/OA3_ED/SPI_CS_ETH3
OA3_RX_ETH3: sheet MCU/PR0_PRU1_GPIO1, sheet ETHERNET/OA3_RX_ETH3
OA3_TX_ETH3: sheet MCU/PR0_PRU1_GPIO2, sheet ETHERNET/OA3_TX_ETH3
P15_TCAL9539: sheet LOAD DRIVERS/SEL0_TPS4HC120, sheet IO Mgmt/P15_TCAL9539
P16_TCAL9539: sheet LOAD DRIVERS/SEL1_TPS4HC120, sheet IO Mgmt/P16_TCAL9539
P23_TXE8116: sheet LOAD DRIVERS/SEL_TPS2HC08, sheet IO Mgmt/P23_TXE8116
PMIC_DIAG: sheet POWER/PMIC_DIAG_OUT, sheet IO Mgmt/PMIC_DIAG_OUT_MUX
PMIC_nINT: sheet POWER/PMIC_INTn, sheet IO Mgmt/PMIC_nINT_MUX
PMIC_nRST: sheet POWER/PMIC_nRST, sheet MCU/PMIC_nRST
PR0_PRU0_GPIO0: sheet MCU/PR0_PRU0_GPIO0, sheet ETHERNET/RX_D0_ETH2
PR0_PRU0_GPIO1: sheet MCU/PR0_PRU0_GPIO1, sheet ETHERNET/RX_D1_ETH2
PR0_PRU0_GPIO2: sheet MCU/PR0_PRU0_GPIO2, sheet ETHERNET/RX_D2_ETH2
PR0_PRU0_GPIO3: sheet MCU/PR0_PRU0_GPIO3, sheet ETHERNET/RX_D3_ETH2
PR0_PRU0_GPIO6: sheet MCU/PR0_PRU0_GPIO6, sheet ETHERNET/RX_CLK_ETH2
PR0_PRU0_GPIO11: sheet MCU/PR0_PRU0_GPIO11, sheet ETHERNET/TX_D0_ETH2
PR0_PRU0_GPIO12: sheet MCU/PR0_PRU0_GPIO12, sheet ETHERNET/TX_D1_ETH2
PR0_PRU0_GPIO13: sheet MCU/PR0_PRU0_GPIO13, sheet ETHERNET/TX_D2_ETH2
PR0_PRU0_GPIO14: sheet MCU/PR0_PRU0_GPIO14, sheet ETHERNET/TX_D3_ETH2
PR0_PRU0_GPIO15: sheet MCU/PR0_PRU0_GPIO15, sheet ETHERNET/TX_EN/TX_CTRL_ETH2
PR0_PRU0_GPIO16: sheet MCU/PR0_PRU0_GPIO16, sheet ETHERNET/TX_CLK_ETH2
PR0_PRU1_GPIO8: sheet MCU/SPI5_SDO, sheet ETHERNET/SPI_POCI_ETH3
PR0_PRU1_GPIO18: sheet CAN/LIN/TXD1_TCAN1046_UART, sheet MCU/UART3_TXD
PR0_PRU1_GPIO19: sheet CAN/LIN/RXD1_TCAN1046_UART, sheet MCU/UART3_RXD
PWM_ETH: R478.2 ; sheet MCU/GPIO74, sheet ETHERNET/PWM_ETH
RESET_ETH: sheet IO Mgmt/P00_TCAL9539, sheet ETHERNET/RESET_ETH1, sheet ETHERNET/RESET_ETH3, sheet ETHERNET/RESET_ETH2
RESET_TPS: sheet POWER/RESET_TPS3762, sheet IO Mgmt/RESET_TPS3762
RGMII1_RD0: sheet MCU/RGMII1_RD0, sheet ETHERNET/RX_D0_ETH1
RGMII1_RD1: sheet MCU/RGMII1_RD1, sheet ETHERNET/RX_D1_ETH1
RGMII1_RD2: sheet MCU/RGMII1_RD2, sheet ETHERNET/RX_D2_ETH1
RGMII1_RD3: sheet MCU/RGMII1_RD3, sheet ETHERNET/RX_D3_ETH1
RGMII1_RXC: sheet MCU/RGMII1_RXC, sheet ETHERNET/RX_CLK_ETH1
RGMII1_TD0: sheet MCU/RGMII1_TD0, sheet ETHERNET/TX_D0_ETH1
RGMII1_TD1: sheet MCU/RGMII1_TD1, sheet ETHERNET/TX_D1_ETH1
RGMII1_TD2: sheet MCU/RGMII1_TD2, sheet ETHERNET/TX_D2_ETH1
RGMII1_TD3: sheet MCU/RGMII1_TD3, sheet ETHERNET/TX_D3_ETH1
RGMII1_TX_CTL: sheet MCU/RGMII1_TX_CTL, sheet ETHERNET/TX_EN/TX_CTRL_ETH1
RGMII1_TXC: sheet MCU/RGMII1_TXC, sheet ETHERNET/TX_CLK_ETH1
RXD2_TCAN1046_UART: sheet CAN/LIN/RXD2_TCAN1046_UART, sheet MCU/UART5_RXD
SAFETY_ERRORn: sheet POWER/SAFETY_ERRORn, sheet MCU/SAFETY_ERRORn
SCLK: sheet LOAD DRIVERS/SCLK_LD, sheet MCU/SPI7_CLK
SCLK_IO: sheet IO Mgmt/SCLK_IO, sheet MCU/SPI6_CLK
SCLK_PMIC: sheet POWER/SCLK_PMIC, sheet MCU/SPI3_CLK
SDFM_CLK2: sheet CAN/LIN/TXD2_TCAN1046_UART, sheet MCU/UART5_TXD
SDI: sheet LOAD DRIVERS/SDI_LD, sheet MCU/SPI7_SDI
SDI_IO: sheet IO Mgmt/SDI_IO, sheet MCU/SPI6_SDI
SDI_PMIC: sheet POWER/SDI_PMIC, sheet MCU/SPI3_SDI
SDO_IO: sheet IO Mgmt/SDO_IO, sheet MCU/SPI6_SDO
SDO_LD: sheet LOAD DRIVERS/SDO_LD, sheet MCU/SPI7_SDO
SDO_PMIC: sheet POWER/SDO_PMIC, sheet MCU/SPI3_SDO
SPI0_CLK: sheet CAN/LIN/TXD2_TLIN1024A, sheet MCU/LIN3_TXD
SPI0_D0: sheet IO Mgmt/PMIC_nINT_MCU, sheet MCU/GPIO13
SPI5_CLK: sheet MCU/SPI5_CLK, sheet ETHERNET/SPI_SCLK_ETH3
SPI5_SDI: sheet MCU/SPI5_SDI, sheet ETHERNET/SPI_PICO_ETH3
SPI7_CS2: sheet IO Mgmt/CS_LD_2_MCU, sheet MCU/SPI7_CS2
SPI7_CS5: sheet LOAD DRIVERS/CS_LD_5, sheet MCU/SPI7_CS5
WAKE: sheet LOAD DRIVERS/WAKE_TPS1214, sheet IO Mgmt/P02_TCAL9539, sheet IO Mgmt/WAKE_TPS1214
WAKE2: D40.1(K) ; sheet POWER/PMIC_WAKE2, sheet IO Mgmt/PMIC_WAKE2

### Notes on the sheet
- Either R479 or R478 should be connected. R478 is used for AVB applications.
- TCAL9539 used to hold signals for LPM operation
- Note Color Guide:
  Green notes --> layout guidelines
  Yellow notes --> design considerations

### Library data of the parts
D40 = CMP-0028880-3: Diode, Schottky, 20 V, 0.5 A, AEC-Q101, SOD-523; Manufacturer: ON Semiconductor; Green_Lifecycle: Not Set; Vr_V: 20V; TJmax_C: 125°C; SizeArea_mm2: 1.53; SizeZ_mm: 0.65; Green_REACh: Incomplete; AEC Qualified: Y; AEC Category: Q101; Io_A: 500mA; Value: 20V; Vf_V: 480mV; Value1: 0.5A; SizeY_mm: 0.9; SizeX_mm: 1.7; Value2: 0.48V; SizeAreaWB_mm2: 5.13
R478 = CMP-0025885-5: RES, 0, 5%, 0.1 W, 0603; Manufacturer: Yageo; Power_W: 100mW; TempCo: 200 ppm/C; Value_Code: 0000; Value: 0; EIA_Code: E24; SizeX_mm: 1.6; SizeZ_mm: 1; Value2: 0.1W; SizeArea_mm2: 1.28; AEC Qualified: N; VDC_V: 75V; AEC Category: Q200; SizeY_mm: 0.8; SizeAreaWB_mm2: 4.68

## Sheet Power Overview.SchDoc
size 431 x 279 mm; Date: Not shown in title block; ApprovedBy: Not shown in title block; CheckedBy: Not shown in title block; Author: Not shown in title block; CompanyName: Not shown in title block; Engineer: Not shown in title block; Organization: Not shown in title block; Address1: Not shown in title block; Address2: Not shown in title block; Address3: Not shown in title block; Address4: Not shown in title block; DocumentNumber: 1; Revision: Use project parameter SCH_Rev; SheetNumber: 2; SheetTotal: 30; PageSetup: Record=PageOptions¦CenterHorizontal=True¦CenterVertical=True¦PrintScale=1.00¦XCorrection=1.00¦YCorrection=1.00¦PrintKind=0¦BorderSize=5000000¦LeftOffset=0¦BottomOffset=0¦Orientation=2¦PaperLength=1000¦PaperWidth=1000¦Scale=100¦PaperSource=15¦PrintQuality=600¦MediaType=1¦DitherType=10¦PaperKind=Letter¦PrintScaleMode=1
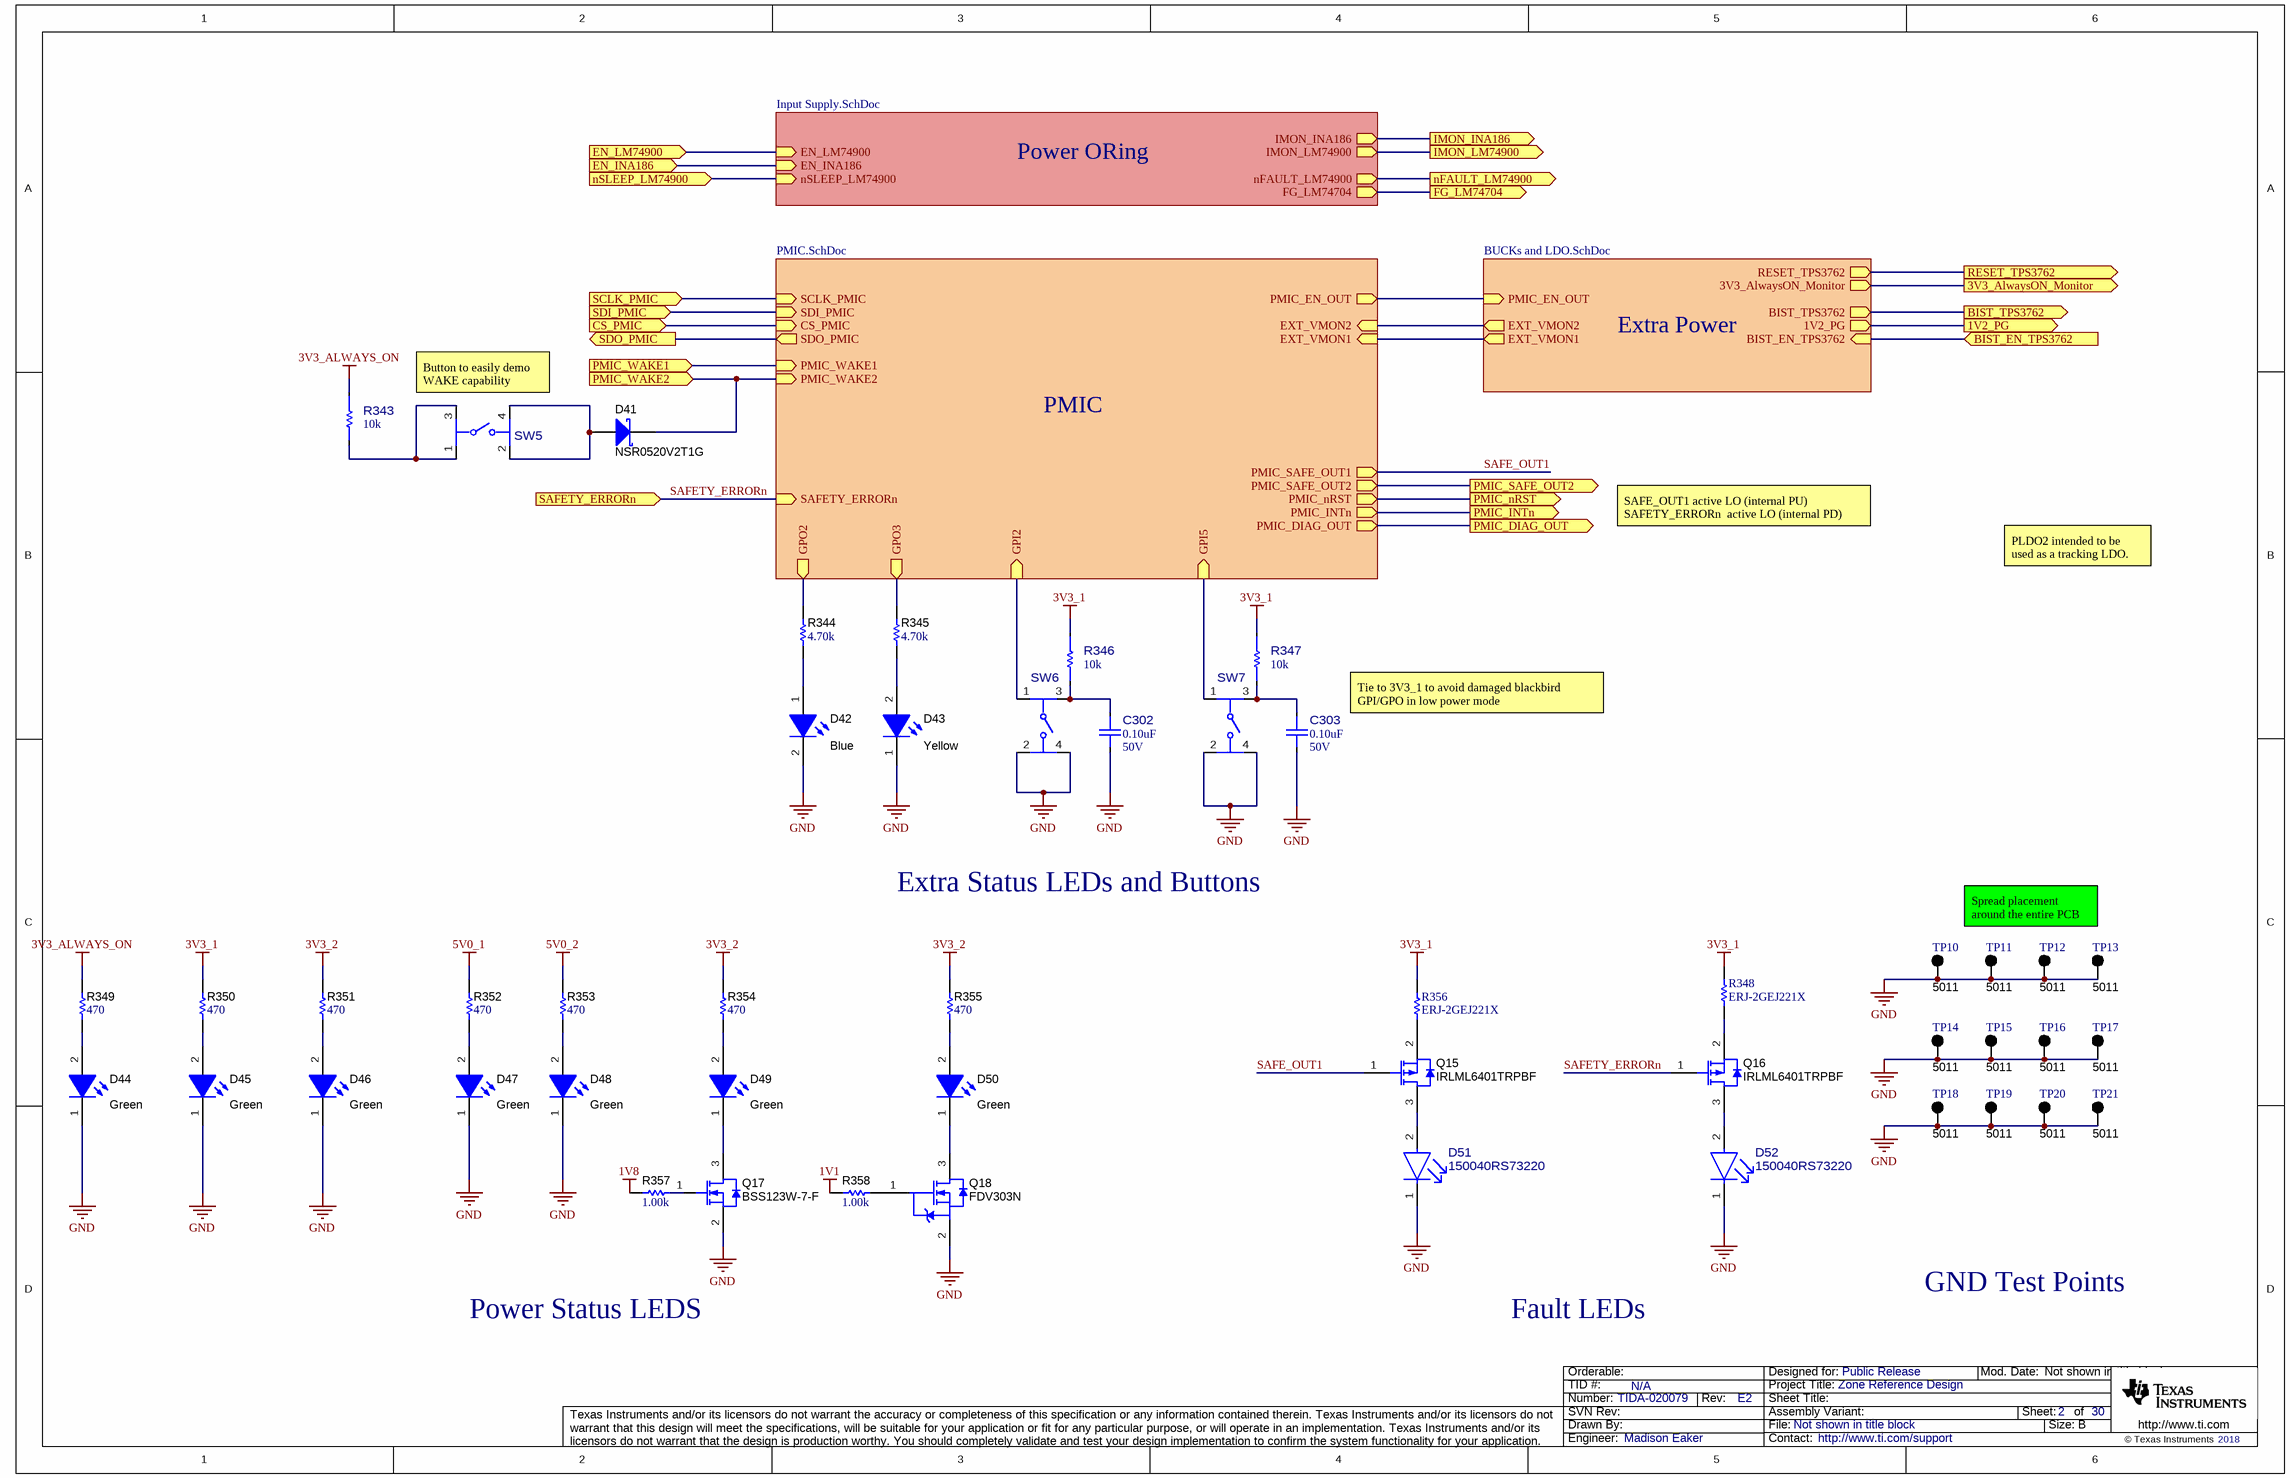
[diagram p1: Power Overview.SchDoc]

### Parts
C302  ValueDisplayed: 0.10uF  VDC_V: 50V  [FP-GRM155R71H104KE14D_0402-MFG]  (hidden comment: GRM155R71H104KE14D)
C303  ValueDisplayed: 0.10uF  VDC_V: 50V  [FP-GRM155R71H104KE14D_0402-MFG]  (hidden comment: GRM155R71H104KE14D)
D41  NSR0520V2T1G  [SOD-523]
D42  value Blue  [LTST-C193_Blue]  (hidden comment: LTST-C193TBKT-5A)
D43  value Yellow  [WL-SMCW_YELLOW]  (hidden comment: 150060YS75000)
D44  value Green  [WL-SMCW_GREEN]  (hidden comment: 150060VS75000)
D45  value Green  [WL-SMCW_GREEN]  (hidden comment: 150060VS75000)
D46  value Green  [WL-SMCW_GREEN]  (hidden comment: 150060VS75000)
D47  value Green  [WL-SMCW_GREEN]  (hidden comment: 150060VS75000)
D48  value Green  [WL-SMCW_GREEN]  (hidden comment: 150060VS75000)
D49  value Green  [WL-SMCW_GREEN]  (hidden comment: 150060VS75000)
D50  value Green  [WL-SMCW_GREEN]  (hidden comment: 150060VS75000)
D51  150040RS73220  [FP-150040RS73220_0402-MFG]
D52  150040RS73220  [FP-150040RS73220_0402-MFG]
Q15  IRLML6401TRPBF  [SOT-23]
Q16  IRLML6401TRPBF  [SOT-23]
Q17  BSS123W-7-F  [SOT-323]
Q18  FDV303N  [SOT-23]
R343  value 10k  [FP-RC0402JR-0710KL_0402-MFG]  (hidden comment: RC0402JR-0710KL)
R344  ValueDisplayed: 4.70k  [0603]  (hidden comment: RT0603BRD074K7L)
R345  ValueDisplayed: 4.70k  [0603]  (hidden comment: RT0603BRD074K7L)
R346  value 10k  [FP-RC0402JR-0710KL_0402-MFG]  (hidden comment: RC0402JR-0710KL)
R347  value 10k  [FP-RC0402JR-0710KL_0402-MFG]  (hidden comment: RC0402JR-0710KL)
R348  ERJ-2GEJ221X  [RESC1005X40X25LL05T05]
R349  ValueDisplayed: 470  [0603]  (hidden comment: RT0603BRD07470RL)
R350  ValueDisplayed: 470  [0603]  (hidden comment: RT0603BRD07470RL)
R351  ValueDisplayed: 470  [0603]  (hidden comment: RT0603BRD07470RL)
R352  ValueDisplayed: 470  [0603]  (hidden comment: RT0603BRD07470RL)
R353  ValueDisplayed: 470  [0603]  (hidden comment: RT0603BRD07470RL)
R354  ValueDisplayed: 470  [0603]  (hidden comment: RT0603BRD07470RL)
R355  ValueDisplayed: 470  [0603]  (hidden comment: RT0603BRD07470RL)
R356  ERJ-2GEJ221X  [RESC1005X40X25LL05T05]
R357  ValueDisplayed: 1.00k  [0402]  (hidden comment: ERJ-2RKF1001X)
R358  ValueDisplayed: 1.00k  [0402]  (hidden comment: ERJ-2RKF1001X)
SW5  430182050816  [FP-430182050816_SMT_SW_6MM2_6MM2-MFG]  (value not drawn)
SW6  430182050816  [FP-430182050816_SMT_SW_6MM2_6MM2-MFG]  (value not drawn)
SW7  430182050816  [FP-430182050816_SMT_SW_6MM2_6MM2-MFG]  (value not drawn)
TP10  5011  [Keystone5011]
TP11  5011  [Keystone5011]
TP12  5011  [Keystone5011]
TP13  5011  [Keystone5011]
TP14  5011  [Keystone5011]
TP15  5011  [Keystone5011]
TP16  5011  [Keystone5011]
TP17  5011  [Keystone5011]
TP18  5011  [Keystone5011]
TP19  5011  [Keystone5011]
TP20  5011  [Keystone5011]
TP21  5011  [Keystone5011]

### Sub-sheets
Extra Power = BUCKs and LDO.SchDoc: 1V2_PG (out), PMIC_EN_OUT (in), EXT_VMON1 (out), EXT_VMON2 (out), BIST_EN_TPS3762 (in), BIST_TPS3762 (out), 3V3_AlwaysON_Monitor (out), RESET_TPS3762 (out)
PMIC = PMIC.SchDoc: PMIC_SAFE_OUT1 (out), PMIC_DIAG_OUT (out), PMIC_EN_OUT (out), SCLK_PMIC (in), SDI_PMIC (in), SDO_PMIC (out), CS_PMIC (in), PMIC_WAKE2 (in), PMIC_WAKE1 (in), PMIC_SAFE_OUT2 (out), PMIC_nRST (out), PMIC_INTn (out), EXT_VMON1 (in), SAFETY_ERRORn (in), EXT_VMON2 (in), GPI2 (in), GPO2 (out), GPO3 (out), GPI5 (in)
Power ORing = Input Supply.SchDoc: EN_INA186 (in), EN_LM74900 (in), nSLEEP_LM74900 (in), FG_LM74704 (out), IMON_LM74900 (out), IMON_INA186 (out), nFAULT_LM74900 (out)

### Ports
1V2_PG (out), 3V3_AlwaysON_Monitor (out), BIST_EN_TPS3762 (in), BIST_TPS3762 (out), CS_PMIC (in), EN_INA186 (in), EN_LM74900 (in), FG_LM74704 (out), IMON_INA186 (out), IMON_LM74900 (out), nFAULT_LM74900 (out), nSLEEP_LM74900 (in), PMIC_DIAG_OUT (out), PMIC_INTn (out), PMIC_nRST (out), PMIC_SAFE_OUT2 (out), PMIC_WAKE1 (in), PMIC_WAKE2 (in), RESET_TPS3762 (out), SAFETY_ERRORn (in), SCLK_PMIC (in), SDI_PMIC (in), SDO_PMIC (out)

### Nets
1V1: R358.1
1V8: R357.1
3V3_1: R346.1 R347.1 R348.2 R350.2 R356.2
3V3_2: R351.1 R354.1 R355.1
3V3_ALWAYS_ON: R343.1 R349.1
5V0_1: R352.2
5V0_2: R353.2
GND: C302.2 C303.2 D42.2(K) D43.1(K) D44.1(K) D45.1(K) D46.1(K) D47.1(K) D48.1(K) D51.1(CATHODE) D52.1(CATHODE) Q17.2(S) Q18.2(S) SW6.2 SW6.4 SW7.2 SW7.4 TP10.1 TP11.1 TP12.1 TP13.1 TP14.1 TP15.1 TP16.1 TP17.1 TP18.1 TP19.1 TP20.1 TP21.1
1V2_PG: port 1V2_PG, sheet Extra Power/1V2_PG
3V3_ADC: port 3V3_AlwaysON_Monitor, sheet Extra Power/3V3_AlwaysON_Monitor
ADC0_AIN0: port IMON_LM74900, sheet Power ORing/IMON_LM74900
ADC0_AIN1: port IMON_INA186, sheet Power ORing/IMON_INA186
BIST_EN_TPS3762: port BIST_EN_TPS3762, sheet Extra Power/BIST_EN_TPS3762
BIST_TPS3762: port BIST_TPS3762, sheet Extra Power/BIST_TPS3762
CS_PMIC: port CS_PMIC, sheet PMIC/CS_PMIC
EN_INA186: port EN_LM74900, port EN_INA186, sheet Power ORing/EN_INA186, sheet Power ORing/EN_LM74900
EPWM5_A: port nFAULT_LM74900, sheet Power ORing/nFAULT_LM74900
EQEP0_A: port nSLEEP_LM74900, sheet Power ORing/nSLEEP_LM74900
EXT_VMON1: sheet PMIC/EXT_VMON1, sheet Extra Power/EXT_VMON1
EXT_VMON2: sheet PMIC/EXT_VMON2, sheet Extra Power/EXT_VMON2
FETGOOD: port FG_LM74704, sheet Power ORing/FG_LM74704
GPI2: SW6.1 ; sheet PMIC/GPI2
GPI5: SW7.1 ; sheet PMIC/GPI5
GPO2: R344.2 ; sheet PMIC/GPO2
GPO3: R345.2 ; sheet PMIC/GPO3
INH_TCAN1043A: port PMIC_WAKE1, sheet PMIC/PMIC_WAKE1
LHI_HCS: port PMIC_SAFE_OUT2, sheet PMIC/PMIC_SAFE_OUT2
PMIC_DIAG: port PMIC_DIAG_OUT, sheet PMIC/PMIC_DIAG_OUT
PMIC_EN_OUT: sheet PMIC/PMIC_EN_OUT, sheet Extra Power/PMIC_EN_OUT
PMIC_nINT: port PMIC_INTn, sheet PMIC/PMIC_INTn
PMIC_nRST: port PMIC_nRST, sheet PMIC/PMIC_nRST
RESET_TPS: port RESET_TPS3762, sheet Extra Power/RESET_TPS3762
SAFE_OUT1: Q15.1(G) ; sheet PMIC/PMIC_SAFE_OUT1
SAFETY_ERRORn: Q16.1(G) ; port SAFETY_ERRORn, sheet PMIC/SAFETY_ERRORn
SCLK_PMIC: port SCLK_PMIC, sheet PMIC/SCLK_PMIC
SDI_PMIC: port SDI_PMIC, sheet PMIC/SDI_PMIC
SDO_PMIC: port SDO_PMIC, sheet PMIC/SDO_PMIC
WAKE2: D41.1(K) ; port PMIC_WAKE2, sheet PMIC/PMIC_WAKE2
NetC302_1: C302.1 R346.2 SW6.3
NetC303_1: C303.1 R347.2 SW7.3
NetD41_2: D41.2(A) SW5.2 SW5.4
NetD42_1: D42.1(A) R344.1
NetD43_2: D43.2(A) R345.1
NetD44_2: D44.2(A) R349.2
NetD45_2: D45.2(A) R350.1
NetD46_2: D46.2(A) R351.2
NetD47_2: D47.2(A) R352.1
NetD48_2: D48.2(A) R353.1
NetD49_1: D49.1(K) Q17.3(D)
NetD49_2: D49.2(A) R354.2
NetD50_1: D50.1(K) Q18.3(D)
NetD50_2: D50.2(A) R355.2
NetD51_2: D51.2(ANODE) Q15.3(D)
NetD52_2: D52.2(ANODE) Q16.3(D)
NetQ15_2: Q15.2(S) R356.1
NetQ16_2: Q16.2(S) R348.1
NetQ17_1: Q17.1(G) R357.2
NetQ18_1: Q18.1(G) R358.2
NetR343_2: R343.2 SW5.1 SW5.3

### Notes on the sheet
- (near SW5) Button to easily demo WAKE capability
- SAFE_OUT1 active LO (internal PU)
  SAFETY_ERRORn  active LO (internal PD)
- PLDO2 intended to be used as a tracking LDO.
- Tie to 3V3_1 to avoid damaged blackbird GPI/GPO in low power mode
- Extra Status LEDs and Buttons
- Spread placement around the entire PCB
- GND Test Points
- Power Status LEDS
- Fault LEDs

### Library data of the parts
C302 C303 = CMP-0096855-1: Chip Multilayer Ceramic Capacitors for General Purpose, 0402, 0.10uF, X7R, 15%, 10%, 50V; Manufacturer: Murata; SizeZ_mm: 0.55mm; Value: 100nF; AEC Qualified: No
D41 = CMP-0028880-3: as D40 on sheet Zone Reference Design Top Sheet
D42 = CMP-0002938-2: LED, Blue, SMD; Manufacturer: Lite-On; Io_A: 5mA; Power_TotalModule: 76mW; Tjmax_C: 80°C; Value1: 0.076W; U/M: EA; Angle: 130; Ir_A: 10µA; Vf_V: 2.8V; Type: InGaN; LuminousIntensity_IV: 15
D43 = CMP-0002892-2: LED, Yellow, SMD; Manufacturer: Wurth Elektronik; Io_A: 20mA; Value1: W; U/M: EA; Vf_V: 2V; Type: AlInGaP
D44-D50 = CMP-0002894-2: LED, Green, SMD; Manufacturer: Wurth Elektronik; Type: AlInGaP; Value2: 2V; Io_A: 20mA; Value1: W
D51 D52 = CMP-0122246-1: Red 624nm LED Indication - Discrete 2V 0402 (1005 Metric); Manufacturer: Wurth; Angle: 120°; LambdaP: 632nm; Power_TotalModule: 48mW; SizeZ_mm: 0.35mm; Tjmax_C: 115°C; Vr_V: 5V; AEC Qualified: No; Forward Current: 20mA; Led Orientation: Top View; Luminous Intensity: 110mcd
Q15 Q16 = CMP-0078819-2: MOSFET, P-CH, -12 V, -4.3 A, SOT-23; Alternate Manufacturer: None; Manufacturer: Infineon Technologies; SizeY_mm: 3; ChMode: Enhancement; SizeX_mm: 2.5; QgTyp_nC: 10; ChType: P; AEC Qualified: N; Value2: 10 nC; SizeZ_mm: 1.1; Green_Lifecycle: Active; Vgs_V: -8V; SizeArea_mm2: 7.5; Value: -12V; IdsMax_A: -4.3A; SizeAreaWB_mm2: 14; AEC Category: Q101; Value1: 0.05 ohm; Rdson45_ohm: 0.05; Green_REACh: Passed
Q17 = CMP-0000948-2: MOSFET, N-CH, 100 V, 0.17 A, SOT-323; Alternate Manufacturer: None; Manufacturer: Diodes Inc.; SizeZ_mm: 1.1; ChType: N; Value1: 1; VdsMax_V: 100V; SizeX_mm: 2.2; Vgs_V: 20V; Value: 100V; Rdson45_ohm: 10; SizeArea_mm2: 4.84; AEC Category: Q101; IdsMax_A: 1.7dA; SizeAreaWB_mm2: 10.24; U/M: EA
Q18 = CMP-0000282-1: MOSFET, N-CH, 25 V, 0.68 A, SOT-23; Alternate Manufacturer: None; Manufacturer: Fairchild Semiconductor; SizeZ_mm: 1.1; ChType: N; Value2: 1.64 nC; Value1: 0.4; VdsMax_V: 25V; SizeX_mm: 2.5; SizeY_mm: 3; Vgs_V: 1.5V; Value: 25V; Rdson45_ohm: 0.45; SizeArea_mm2: 7.5; AEC Category: Q101; IdsMax_A: 680mA; SizeAreaWB_mm2: 14; U/M: EA; QgTyp_nC: 1.64
R343 R346 R347 = CMP-0094798-1: Res Thick Film 0402 10K Ohm 5% 0.063W(1/16W) ±100ppm/C Pad SMD T/R; Manufacturer: YAGEO; AEC Qualified: No; Category Cd01000Bfc2916C6: Single Components; SizeZ_mm: 0.4mm; VDC_V: 50V; Category 5C6A91606D4187Ad: Resistors; TempCo: 100ppm/°C; Power_W: 63mW; Category 7542B8484461Ae85: Passive Components
R344 R345 = CMP-0024300-2: RES, 4.70 k, 0.1%, 0.1 W, 0603; Manufacturer: Yageo America; Power_W: 100mW; TempCo: 25 ppm/C; Value_Code: 4k70; U/M: EA; Value: 4.70k; EIA_Code: E192; Res_ohm: 4.7k; SizeX_mm: 1.6; SizeY_mm: 0.8; SizeZ_mm: 1; Value2: 0.1W; SizeArea_mm2: 1.28; VDC_V: 75V; AEC Category: Q200
R348 R356 = CMP-2002-00487-3: Chip Resistor, 220 Ohm, +/- 5%, 100 mW, -55 to 155 degC, 0402 (1005 Metric), RoHS, Tape and Reel; Manufacturer: Basic Passives; Voltage Rating: 50 V; Case\/Package: 0402; Power Rating: 100 mW; Resistance: 220 Ohm
R349-R355 = CMP-0024263-2: RES, 470, 0.1%, 0.1 W, 0603; Manufacturer: Yageo America; Power_W: 100mW; TempCo: 25 ppm/C; Value_Code: 470R; U/M: EA; Value: 470; EIA_Code: E192; SizeX_mm: 1.6; SizeY_mm: 0.8; SizeZ_mm: 1; Value2: 0.1W; SizeArea_mm2: 1.28; VDC_V: 75V; AEC Category: Q200
R357 R358 = CMP-0026657-1: RES, 1.00 k, 1%, 0.1 W, 0402; Manufacturer: Panasonic; Power_W: 100mW; TempCo: 100 ppm/C; Value_Code: 1k00; U/M: EA; Value: 1.00k; EIA_Code: E96; Res_ohm: 1k; SizeX_mm: 1; SizeY_mm: 0.5; SizeZ_mm: 0.6; Value2: 0.1W; VDC_V: 50V; AEC Category: Q200
SW5-SW7 = CMP-0097324-1: Switch Tactile N.O. SPST Round Button Gull Wing 0.05A 12VDC 1000000Cycles 1.57N SMD Reel; Manufacturer: Wurth Electronics; AEC Qualified: No; Operating Force: 160gf; Coil Resistance_ohm: 100mΩ; VDC_V: 12V; Circuit: SPST-NO; SizeZ_mm: 5.15mm; Contact Current Rating: 50mA
TP10-TP21 = CMP-0055148-2: Test Point, Multipurpose, Black, TH; Manufacturer: Keystone Electronics; CNHeader: FALSE; ContactFinish: Silver; Green_REACh: Passed; Green_Lifecycle: Active; CT: TRUE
